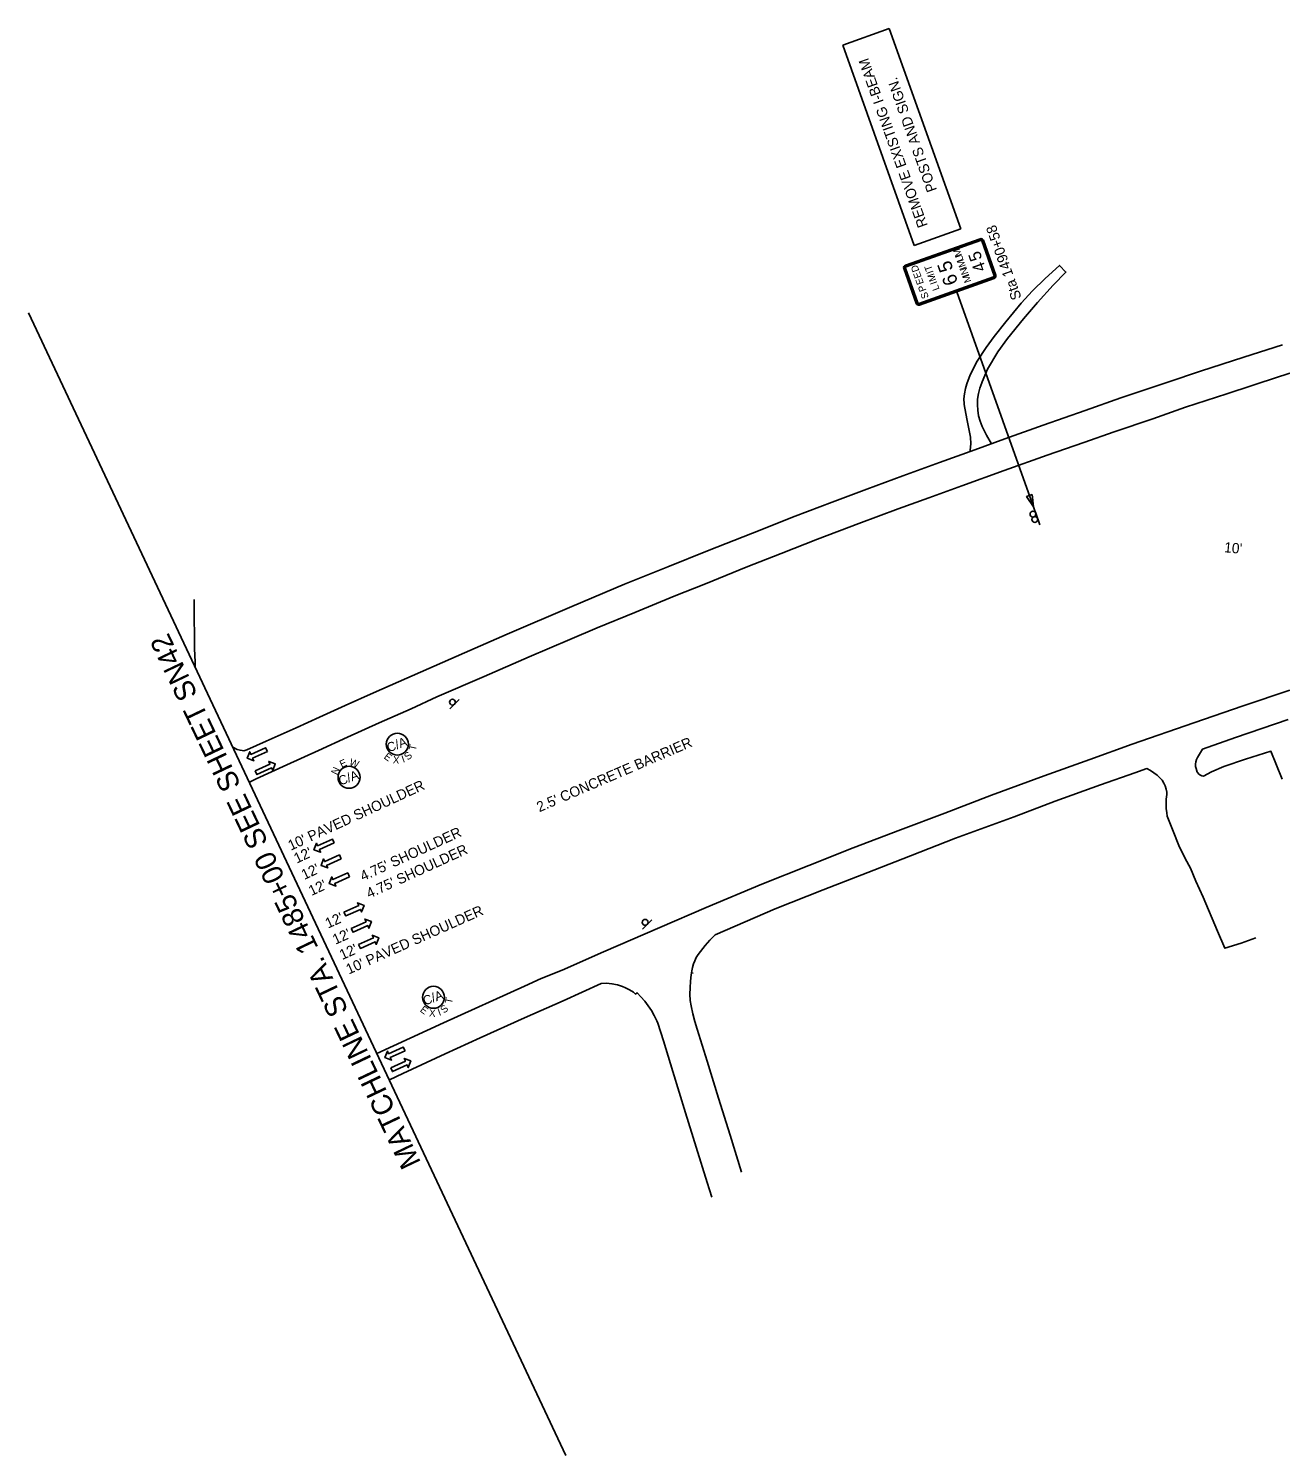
# Model space of a CAD drawing. Extents: x 1795808 to 1797487, y 1187415 to 1188757.
# Drawn here: x 1795808 to 1796661, y 1187415 to 1188387 of the extents above; entities that cross this region are included whole.
import ezdxf

# ---------------------------------------------------------------- set-up
doc = ezdxf.new("R2010")
doc.units = 0
for name, color, linetype in [('RD_EX_Road', 7, 'Continuous'), ('RD_PD_Final_LnLine', 7, 'Continuous'), ('RD_PD_Final_TX', 7, 'Continuous'), ('RD_SHT_MatchLine', 7, 'Continuous'), ('RD_SHT_TX', 7, 'Continuous'), ('RD_Sketch10', 7, 'Continuous'), ('RD_Sketch8', 7, 'Continuous'), ('SN_P_Signs', 7, 'Continuous')]:
    doc.layers.add(name, color=color, linetype=linetype)

# ---------------------------------------------------------------- blocks, each defined once
blk = doc.blocks.new('SARRW2')
at = {"layer": 'RD_PD_Final_LnLine'}
blk.add_lwpolyline([(-12, 1.2), (-12, -1.2), (-2.83, -1.2), (-2.83, -2.83), (0, 0), (-2.83, 2.83), (-2.83, 1.2)], close=True, dxfattribs=at)

msp = doc.modelspace()

# ---------------------------------------------------------------- linework, layer by layer
at = {"layer": 'RD_EX_Road'}
for points in [[(1796464.39, 1188104.28), (1796460.78, 1188110.15), (1796457.92, 1188116.08), (1796456.53, 1188119.63), (1796455.52, 1188123.29), (1796454.9, 1188127.05), (1796454.67, 1188130.84), (1796454.67, 1188130.88), (1796454.82, 1188134.68), (1796455.37, 1188138.44), (1796456.31, 1188142.12), (1796457.62, 1188145.68), (1796457.95, 1188146.44), (1796461.56, 1188155.02), (1796468.65, 1188166.84), (1796475.25, 1188176.02), (1796486.07, 1188189.49), (1796495.59, 1188200.62), (1796506.29, 1188212.28), (1796514.98, 1188221.28), (1796510.75, 1188225.77), (1796500.85, 1188216.92), (1796492.17, 1188208.48), (1796484.53, 1188200.15), (1796474.03, 1188187.32), (1796466.19, 1188177.37), (1796460.75, 1188169.84), (1796454.44, 1188160.5), (1796449.83, 1188151.15), (1796447.55, 1188145.15), (1796446.49, 1188141.81), (1796445.81, 1188138.37), (1796445.53, 1188134.88), (1796445.63, 1188131.38), (1796445.66, 1188131.08), (1796447.42, 1188121.29), (1796450.02, 1188108.74), (1796450.13, 1188104.3), (1796449.84, 1188099.86), (1796449.74, 1188098.97)], [(1795947.24, 1187897.43), (1795950.21, 1187895.94), (1795952.17, 1187895.28), (1795953.51, 1187895.08), (1795954.65, 1187895.02), (1795956.69, 1187895.59), (1795970.06, 1187901.48), (1795990.32, 1187910.7), (1796006.31, 1187917.98), (1796023.87, 1187925.8), (1796043.2, 1187934.49), (1796060.17, 1187941.96), (1796105.21, 1187961.75), (1796134.17, 1187974.47), (1796178.17, 1187993.41), (1796214.18, 1188008.48), (1796243.62, 1188020.35), (1796270.82, 1188031.24), (1796301.52, 1188043.41), (1796330.47, 1188054.78), (1796355.72, 1188064.32), (1796379.28, 1188073.22), (1796403.97, 1188082.48), (1796428.91, 1188091.37), (1796452.86, 1188100.11), (1796473.47, 1188107.56), (1796499.54, 1188116.84), (1796528.18, 1188126.95), (1796552.52, 1188135.54), (1796584.5, 1188146.14), (1796606.72, 1188153.64), (1796636.32, 1188163.25), (1796662.68, 1188171.76)], [(1795958.48, 1187873.54), (1795963.21, 1187875.75), (1795984, 1187885.34), (1796005.63, 1187895.07), (1796025.28, 1187904.19), (1796046.99, 1187914.1), (1796068.78, 1187923.65), (1796086.31, 1187931.68), (1796118.42, 1187945.67), (1796149.21, 1187959.01), (1796176.98, 1187970.78), (1796195.65, 1187978.81), (1796221.17, 1187989.21), (1796248.01, 1188000.4), (1796269.32, 1188008.87), (1796297, 1188020.03), (1796320.99, 1188029.49), (1796345.76, 1188039.12), (1796373.92, 1188049.9), (1796400.61, 1188059.84), (1796421.64, 1188067.49), (1796444.03, 1188075.62), (1796472.87, 1188086.03), (1796502.13, 1188096.44), (1796527.13, 1188105.02), (1796547.83, 1188112.36), (1796574.24, 1188121.33), (1796596.58, 1188129.1), (1796624.72, 1188138.3), (1796659.89, 1188149.79), (1796689.8, 1188159.41)], [(1795920.83, 1187998.02), (1795920.93, 1187984.46), (1795921.11, 1187974.56), (1795921.22, 1187964.61), (1795921.47, 1187955.41), (1795921.5, 1187952.18)], [(1796045.45, 1187688.55), (1796090.88, 1187709.47), (1796146.11, 1187734.53), (1796157.48, 1187739.71), (1796171.64, 1187745.49), (1796199.86, 1187757.91), (1796238.36, 1187774.41), (1796269.89, 1187788.17), (1796307.73, 1187803.94), (1796339.84, 1187816.72), (1796370.13, 1187828.77), (1796402.38, 1187841.15), (1796432.41, 1187852.52), (1796464.25, 1187864.59), (1796500.29, 1187877.84), (1796531.28, 1187889.02), (1796560.15, 1187899.4), (1796602.16, 1187914.08), (1796635.93, 1187925.59), (1796667.63, 1187936.38)], [(1796662.35, 1187875.69), (1796654.76, 1187894.64), (1796637.5, 1187889.13), (1796622.56, 1187884.15), (1796614.34, 1187880.56), (1796608.87, 1187877.73), (1796607.74, 1187877.97), (1796606.67, 1187878.43), (1796605.72, 1187879.1), (1796604.93, 1187879.95), (1796604.33, 1187880.94), (1796604.17, 1187881.3), (1796603.69, 1187882.79), (1796603.43, 1187884.34), (1796603.41, 1187885.91), (1796603.63, 1187887.46), (1796604.07, 1187888.97), (1796604.7, 1187890.32), (1796608.1, 1187896.12), (1796630.49, 1187903.95), (1796666.59, 1187916.29)], [(1796259.94, 1187743.68), (1796260.07, 1187744.91), (1796260.51, 1187747.32), (1796261.17, 1187749.69), (1796262.02, 1187751.87), (1796263.11, 1187754.05), (1796264.4, 1187756.12), (1796265.9, 1187758.05), (1796266.03, 1187758.23), (1796269.14, 1187762.17), (1796272.43, 1187765.97), (1796275.89, 1187769.6), (1796316.81, 1187787.19), (1796349.62, 1187800.25), (1796384.18, 1187813.67), (1796409.05, 1187823.39), (1796439.77, 1187835.47), (1796479.75, 1187849.99), (1796507.8, 1187860.65), (1796538.66, 1187871.83), (1796561.93, 1187879.94), (1796570.13, 1187882.79), (1796572.59, 1187881.48), (1796574.94, 1187879.98), (1796577.14, 1187878.28), (1796579.2, 1187876.39), (1796580.6, 1187874.9), (1796581.7, 1187872.99), (1796582.59, 1187870.97), (1796583.26, 1187868.87), (1796583.69, 1187866.71), (1796583.87, 1187865.08), (1796583.43, 1187861.99), (1796583.3, 1187858.85), (1796583.4, 1187855.72), (1796583.74, 1187852.6), (1796584.11, 1187850.49), (1796588.2, 1187840.08), (1796591.9, 1187830.33), (1796596.25, 1187821.46), (1796599.84, 1187814.86), (1796603.6, 1187806.12), (1796608.45, 1187795.13), (1796618.44, 1187771.99), (1796623.37, 1187760.35), (1796634.36, 1187763.9), (1796644.44, 1187767.46)], [(1796293.92, 1187607.62), (1796286.2, 1187632.86), (1796278.27, 1187658.23), (1796270.56, 1187683.48), (1796263.81, 1187705.14), (1796262.2, 1187710.35), (1796260.81, 1187715.64), (1796259.65, 1187720.99), (1796258.99, 1187724.71), (1796258.81, 1187729.08), (1796258.87, 1187733.45), (1796259.17, 1187737.82), (1796259.7, 1187742.16), (1796259.94, 1187743.68), (1796261.01, 1187743.42)], [(1796053.91, 1187670.56), (1796063.13, 1187674.93), (1796092, 1187688.33), (1796115.77, 1187699.22), (1796146.02, 1187712.84), (1796172.36, 1187724.57), (1796198.19, 1187736.38), (1796201.92, 1187736.44), (1796205.63, 1187736.1), (1796209.29, 1187735.37), (1796212.85, 1187734.26), (1796214.88, 1187733.43), (1796217.66, 1187732.08), (1796220.25, 1187730.38), (1796221.76, 1187729.14), (1796222.7, 1187730.04), (1796225.41, 1187727.24), (1796227.97, 1187724.25), (1796230.35, 1187721.1), (1796232.52, 1187717.82), (1796234.49, 1187714.4), (1796236.25, 1187710.89), (1796236.92, 1187709.39), (1796240.72, 1187697.34), (1796247.18, 1187676.25), (1796255.7, 1187648.22), (1796263.02, 1187624.75), (1796270.47, 1187600.67), (1796273.62, 1187590.73)]]:
    msp.add_lwpolyline(points, dxfattribs=at)
at = {"layer": 'RD_SHT_MatchLine'}
msp.add_line((1795808, 1188193.6), (1796174.25, 1187414.6), dxfattribs=at)
at = {"layer": 'RD_Sketch10'}
msp.add_circle((1796026.42, 1187876.86), 7.5, dxfattribs=at)
at = {"layer": 'RD_Sketch8'}
for centre in [(1796059.35, 1187899.46), (1796084, 1187726.91)]:
    msp.add_circle(centre, 7.5, dxfattribs=at)
at = {"layer": 'SN_P_Signs'}
for p, q in [((1796362.99, 1188376.01), (1796394.66, 1188387.29)), ((1796394.66, 1188387.29), (1796443.31, 1188250.67)), ((1796411.64, 1188239.39), (1796362.99, 1188376.01)), ((1796443.31, 1188250.67), (1796411.64, 1188239.39)), ((1796405.63, 1188225.9), (1796456.5, 1188244.02)), ((1796458.8, 1188242.92), (1796467.25, 1188219.19)), ((1796412.99, 1188199.86), (1796404.53, 1188223.6)), ((1796466.16, 1188216.89), (1796415.29, 1188198.77)), ((1796440.72, 1188207.83), (1796492.95, 1188061.17)), ((1796495.97, 1188052.69), (1796492.95, 1188061.17)), ((1796497.26, 1188049.07), (1796494.24, 1188057.55)), ((1796095.12, 1187923.46), (1796101.49, 1187929.83)), ((1796226.52, 1187773.36), (1796232.89, 1187779.73))]:
    msp.add_line(p, q, dxfattribs=at)
for points in [[(1796405.78, 1188225.48), (1796456.65, 1188243.59)], [(1796406.03, 1188224.77), (1796456.9, 1188242.89)], [(1796457.67, 1188242.52), (1796466.12, 1188218.78)], [(1796458.37, 1188242.77), (1796466.83, 1188219.03)], [(1796413.41, 1188200.01), (1796404.96, 1188223.75)], [(1796414.12, 1188200.26), (1796405.66, 1188224)], [(1796465.76, 1188218.02), (1796414.88, 1188199.9)], [(1796466.01, 1188217.31), (1796415.14, 1188199.19)]]:
    msp.add_lwpolyline(points, dxfattribs=at)
msp.add_lwpolyline([(1796492.13, 1188069.59), (1796492.95, 1188061.17), (1796488.26, 1188068.21)], close=True, dxfattribs=at)
for centre in [(1796492.55, 1188056.27), (1796493.83, 1188052.65), (1796096.89, 1187928.09), (1796228.28, 1187777.99)]:
    msp.add_circle(centre, 2, dxfattribs=at)
for centre, radius, start, end in [((1796457.1, 1188242.32), 1.8, 19.60138, 109.60138), ((1796457.1, 1188242.32), 1.35, 19.60138, 109.60138), ((1796457.1, 1188242.32), 0.6, 19.60138, 109.60138), ((1796406.23, 1188224.21), 1.8, 109.60138, 199.60138), ((1796406.23, 1188224.21), 1.35, 109.60138, 199.60138), ((1796406.23, 1188224.21), 0.6, 109.60138, 199.60138), ((1796465.55, 1188218.58), 0.6, 289.60138, 19.60138), ((1796465.55, 1188218.58), 1.35, 289.60138, 19.60138), ((1796465.55, 1188218.58), 1.8, 289.60138, 19.60138), ((1796414.68, 1188200.47), 1.35, 199.60138, 289.60138), ((1796414.68, 1188200.47), 0.6, 199.60138, 289.60138), ((1796414.68, 1188200.47), 1.8, 199.60138, 289.60138)]:
    msp.add_arc(centre, radius, start, end, dxfattribs=at)

# ---------------------------------------------------------------- block references
at = {"layer": 'RD_PD_Final_LnLine'}
for p, xscale, yscale, rotation in [((1795957.06, 1187889.82), 1.2000000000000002, 1.2000000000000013, -155.65820398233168), ((1795976.19, 1187886.02), 1.1999999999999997, 1.2000000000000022, 24.34179601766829), ((1796002.55, 1187827.48), 1.2000000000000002, 1.2000000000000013, -155.65820398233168), ((1796007.4, 1187816.76), 1.2000000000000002, 1.2000000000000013, -155.65820398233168), ((1796012.98, 1187804.44), 1.2000000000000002, 1.2000000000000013, -155.65820398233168), ((1796036.69, 1187789.58), 1.1999999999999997, 1.2000000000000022, 24.34179601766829), ((1796041.69, 1187778.52), 1.1999999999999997, 1.2000000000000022, 24.34179601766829), ((1796046.7, 1187767.47), 1.1999999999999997, 1.2000000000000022, 24.34179601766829), ((1796050.88, 1187685.77), 1.2000000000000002, 1.2000000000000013, -155.65820398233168), ((1796068.52, 1187683.53), 1.1999999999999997, 1.2000000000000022, 24.34179601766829)]:
    msp.add_blockref('SARRW2', p, dxfattribs=dict(at, xscale=xscale, yscale=yscale, rotation=rotation))

# ---------------------------------------------------------------- texts
at = {"layer": 'RD_PD_Final_TX'}
for s, rotation, p in [("10'", 354.65568, (1796622.63, 1188030.33)), ("2.5' CONCRETE BARRIER", 23.30014, (1796156.13, 1187853.01)), ("10' PAVED SHOULDER", 24.66446, (1795986.79, 1187826.8)), ("4.75' SHOULDER", 24.58479, (1796035.94, 1187805.93)), ("4.75' SHOULDER", 24.58479, (1796040.18, 1187794.2)), ("12'", 25.10508, (1795990.86, 1187818.01)), ("12'", 25.08555, (1795995.91, 1187806.85)), ("12'", 25.07394, (1796000.85, 1187795.93)), ("12'", 24.23615, (1796012.1, 1187773.7)), ("10' PAVED SHOULDER", 23.99842, (1796026.28, 1187742.41)), ("12'", 24.21083, (1796017.1, 1187762.68)), ("12'", 24.22081, (1796021.81, 1187752.27))]:
    msp.add_text(s, height=7, rotation=rotation, dxfattribs=at).set_placement(p)
at = {"layer": 'RD_SHT_TX'}
msp.add_text('MATCHLINE STA. 1485+00 SEE SHEET SN42', height=14.1726, rotation=115.4982, dxfattribs=at).set_placement((1796075.66, 1187614.24))
at = {"layer": 'RD_Sketch10'}
for s, height, rotation, p in [('E', 5, 24.21873, (1796021.38, 1187883.23)), ('W', 5, 339.18829, (1796026.17, 1187885.23)), ('N', 5, 64.75544, (1796018.41, 1187878.04)), ('C/A', 6.25, 19.88568, (1796020.56, 1187871.25))]:
    msp.add_text(s, height=height, rotation=rotation, dxfattribs=at).set_placement(p)
at = {"layer": 'RD_Sketch8'}
for s, height, rotation, p in [('C/A', 6.25, 19.88568, (1796053.5, 1187893.86)), ('T', 5, 78.07082, (1796071.9, 1187894.74)), ('E', 5, 323.09692, (1796049.74, 1187890.11)), ('X', 5, 355.52629, (1796056.16, 1187886.42)), ('I', 5, 19.68629, (1796063.24, 1187886.78)), ('S', 5, 41.67812, (1796066.61, 1187888.19)), ('C/A', 6.25, 19.88568, (1796078.14, 1187721.3)), ('T', 5, 78.07082, (1796096.54, 1187722.18)), ('E', 5, 323.09692, (1796074.38, 1187717.56)), ('X', 5, 355.52629, (1796080.8, 1187713.87)), ('I', 5, 19.68629, (1796087.88, 1187714.22)), ('S', 5, 41.67812, (1796091.26, 1187715.63))]:
    msp.add_text(s, height=height, rotation=rotation, dxfattribs=at).set_placement(p)
at = {"layer": 'SN_P_Signs'}
for s, height, rotation, p in [('REMOVE EXISTING I-BEAM', 6.9998, 109.60146, (1796420.96, 1188253.06)), ('POSTS AND SIGN. ', 6.9998, 109.60146, (1796427.2, 1188277.26)), ('Sta 1490+58', 7, 109.60146, (1796484.88, 1188203.73)), ('M', 4.8, 109.60138, (1796444.27, 1188232.75)), ('U', 4.8, 109.60138, (1796445.49, 1188229.32)), ('M', 4.8, 109.60138, (1796446.87, 1188225.44)), ('5', 8.4, 109.60138, (1796458.15, 1188230.43)), ('D', 4.8, 109.60138, (1796415.21, 1188222.24)), ('E', 4.8, 109.60138, (1796416.73, 1188217.95)), ('T', 4.8, 109.60138, (1796424.23, 1188222.83)), ('I', 4.8, 109.60138, (1796424.84, 1188221.12)), ('M', 4.8, 109.60138, (1796426.74, 1188215.79)), ('5', 9.6, 109.60138, (1796438.44, 1188223.19)), ('6', 9.6, 109.60138, (1796441.67, 1188214.12)), ('I', 4.8, 109.60138, (1796447.44, 1188223.85)), ('N', 4.8, 109.60138, (1796448.66, 1188220.43)), ('I', 4.8, 109.60138, (1796449.22, 1188218.84)), ('M', 4.8, 109.60138, (1796450.6, 1188214.96)), ('4', 8.4, 109.60138, (1796460.75, 1188223.14)), ('E', 4.8, 109.60138, (1796418.26, 1188213.67)), ('P', 4.8, 109.60138, (1796419.97, 1188208.87)), ('I', 4.8, 109.60138, (1796427.43, 1188213.84)), ('L', 4.8, 109.60138, (1796428.95, 1188209.59)), ('S', 4.8, 109.60138, (1796421.68, 1188204.07))]:
    msp.add_text(s, height=height, rotation=rotation, dxfattribs=at).set_placement(p)

doc.saveas('drawing.dxf')
